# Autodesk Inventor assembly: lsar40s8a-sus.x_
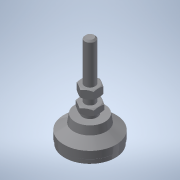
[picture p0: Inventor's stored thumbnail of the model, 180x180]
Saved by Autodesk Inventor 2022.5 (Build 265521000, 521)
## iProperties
Part Number: lsar40s8a-sus.x_
Material: 一般
Document SubType Name: Assembly
Designer: ImaoCorp
Sending System: SOLIDWORKS 2017-2017317
MC: AMD64
MC_MODEL: Intel64 Family 6 Model 60 Stepping 3, GenuineIntel
OS: Windows_NT
FRU: Parasolid Version 29.0, build 201,  4-17-2017
FORMAT: text
GUISE: transmit
KEY: lsar40s8a-sus
FILE: lsar40s8a-sus.x_t
DATE: Mon Jul 01 18:01:52 2019
Author: ImaoCorp
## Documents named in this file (3)
- X:\14_SW2022-Inv2022\00_全2023-1023新製品(TCC)まで\l\lsar40s8a-sus\LSAR40S8A-SUS.iam
- X:\14_SW2022-Inv2022\00_全2023-1023新製品(TCC)まで\l\lsar40s8a-sus\lsar40s8a-sus_01.ipt
- X:\14_SW2022-Inv2022\00_全2023-1023新製品(TCC)まで\l\lsar40s8a-sus\lsar40s8a-sus_02.ipt
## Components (2 placed, 2 different names)
1. lsar40s8a-sus_01
2. lsar40s8a-sus_02
